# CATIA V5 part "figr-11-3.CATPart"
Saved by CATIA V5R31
Part number: Part1
Bounding box of the stored display mesh (mm): x -50 to 50, y -98.731 to 72.975, z 0 to 120
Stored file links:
  D:\PROJECTS\Project 2021\US EDITION\CATIA V5 6R 2021\Resources\Part Files\c11_catia_v5_6r2021_prt\figr-11-3.CATPart
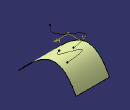
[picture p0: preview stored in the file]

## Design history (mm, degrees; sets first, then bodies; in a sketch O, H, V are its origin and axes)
Set1
  Sketch1 on yz-plane, origin (0, 0, 0), H (0, 1, 0), V (0, 0, 1)
    spline S1 through (-98.7309, 0) (-73.2816, 27.1192) (0, 74.8227) (72.975, 18.624)
    point P1 (-98.7309, 0)
    point P2 (0, 74.8227)
    coincidence: P1 H, P2 V
  Extrude1: Element1 Sketch1, Lim1 50, Lim2 50, Direction yz-plane
  Plane1: type Offset, RefPlane xy-plane, Offset 120
  Sketch2 on Plane1, origin (0, 0, 120), H (1, 0, 0), V (0, 1, 0)
    spline S1 through (28.7787, 44.6229) (-22.3035, 19.7059) (20.5049, -22.8447) (5.396, -48.9118)
  Project1: ToProject Sketch2, Support Extrude1
Body1 (main body)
